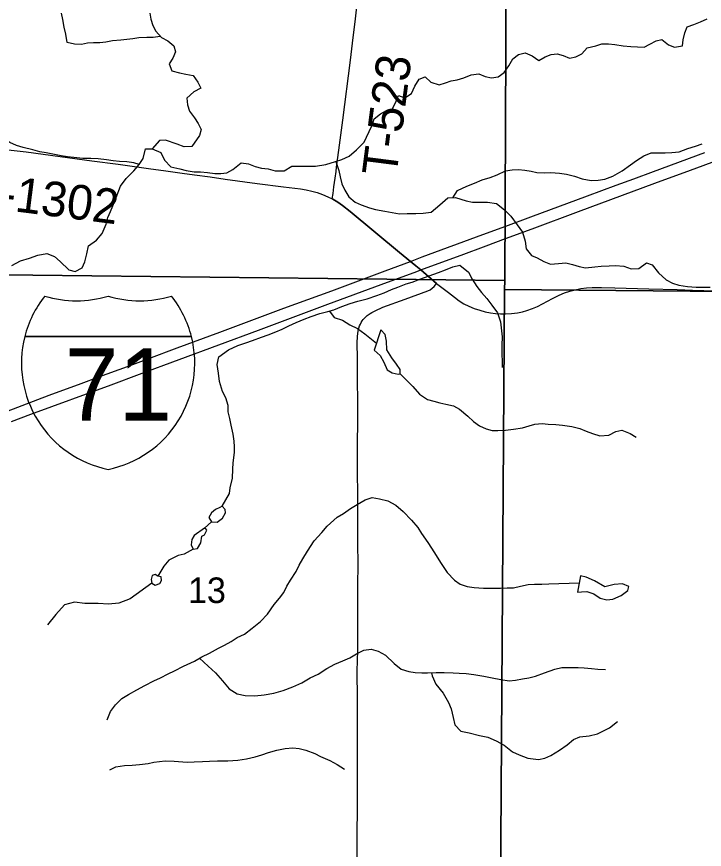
# Model space of a CAD drawing. Extents: x 0 to 34, y 0 to 22.
# Drawn here: x 10.791 to 11.919, y 10.337 to 11.702 of the extents above; entities that cross this region are included whole.
import ezdxf

# ---------------------------------------------------------------- set-up
doc = ezdxf.new("R2010")
doc.units = 0
for name, color, linetype in [('GM_X_County_Road', 7, 'Continuous'), ('GM_X_County_Road_Text', 7, 'Continuous'), ('GM_X_Interstate_Route', 7, 'Continuous'), ('GM_X_Interstate_Shield', 7, 'Continuous'), ('GM_X_Minor_Lake', 7, 'Continuous'), ('GM_X_Minor_River', 7, 'Continuous'), ('GM_X_Section', 7, 'Continuous'), ('GM_X_Section_Text', 7, 'Continuous'), ('GM_X_Township_Road', 7, 'Continuous'), ('GM_X_Township_Road_Text', 7, 'Continuous')]:
    doc.layers.add(name, color=color, linetype=linetype)

msp = doc.modelspace()

# ---------------------------------------------------------------- linework, layer by layer
at = {"layer": 'GM_X_County_Road'}
for points in [[(10.6295, 11.5003), (10.634, 11.4999), (10.6679, 11.4958), (10.7358, 11.4882), (10.782, 11.4831), (10.8067, 11.4801), (10.8621, 11.4725), (10.9144, 11.4654), (10.9576, 11.4597), (11.0073, 11.453), (11.0357, 11.449), (11.0621, 11.4454), (11.0825, 11.4426), (11.1082, 11.4391), (11.133, 11.4354), (11.1854, 11.4283), (11.2285, 11.4229), (11.2563, 11.4194), (11.2655, 11.4179), (11.2747, 11.4158), (11.2837, 11.4133), (11.2925, 11.4102), (11.3012, 11.4065), (11.3083, 11.403)], [(11.3083, 11.403), (11.3096, 11.4024), (11.3177, 11.3976), (11.3254, 11.3923), (11.3376, 11.3826), (11.4189, 11.3152), (11.4365, 11.3005), (11.4452, 11.2933), (11.4534, 11.2865), (11.4796, 11.2646)], [(11.4796, 11.2646), (11.4988, 11.2494), (11.5086, 11.2417), (11.5163, 11.2362), (11.5242, 11.2313), (11.5326, 11.227), (11.5412, 11.2234), (11.5502, 11.2204), (11.5593, 11.2181), (11.5678, 11.2163), (11.5762, 11.2152), (11.5841, 11.2147), (11.5924, 11.2145)], [(11.5924, 11.2145), (11.6025, 11.2152), (11.6119, 11.2165), (11.6203, 11.218), (11.6273, 11.2199), (11.6365, 11.2232), (11.6448, 11.2269), (11.6532, 11.2309), (11.6696, 11.2398), (11.6807, 11.2453), (11.6892, 11.2488), (11.698, 11.2518), (11.7069, 11.2542), (11.716, 11.256), (11.7252, 11.2571), (11.7345, 11.2576), (11.7499, 11.2577), (11.7716, 11.2571), (11.8275, 11.2555), (11.8741, 11.2543), (11.8989, 11.2535), (11.9362, 11.2521)]]:
    msp.add_lwpolyline(points, dxfattribs=at)
at = {"layer": 'GM_X_Interstate_Route'}
for points in [[(10.7745, 11.0548), (10.8442, 11.0812), (10.8967, 11.1005), (10.9258, 11.1112), (10.9725, 11.1284), (11.0074, 11.1415), (11.054, 11.159), (11.124, 11.1846), (11.1764, 11.2043), (11.2288, 11.2238), (11.3076, 11.2525), (11.395, 11.285), (11.4365, 11.3005), (11.4561, 11.3078), (11.5552, 11.3445), (11.5928, 11.3584), (11.6338, 11.3736), (11.7271, 11.408), (11.7737, 11.4253), (11.8029, 11.4361), (11.8349, 11.448), (11.9194, 11.4792)], [(10.7824, 11.038), (10.8144, 11.0501), (10.9457, 11.0984), (10.9922, 11.1158), (11.1876, 11.188), (11.24, 11.2073), (11.3011, 11.2303), (11.3886, 11.2625), (11.4469, 11.284), (11.4534, 11.2865), (11.476, 11.2949), (11.5198, 11.311), (11.5606, 11.326), (11.5927, 11.3379), (11.6363, 11.3541), (11.7121, 11.3823), (11.8374, 11.4286), (11.8957, 11.4501), (11.9773, 11.4804)]]:
    msp.add_lwpolyline(points, dxfattribs=at)
at = {"layer": 'GM_X_Interstate_Shield'}
for p, q in [((10.8043, 11.1773), (11.0775, 11.1773)), ((11.0775, 11.1773), (10.8043, 11.1773)), ((11.0775, 11.1773), (10.8043, 11.1773))]:
    msp.add_line(p, q, dxfattribs=at)
for centre, start, end in [((10.9764, 11.1337), 141.669, 165.8066), ((10.889, 11.4137), 253.0091, 286.9909), ((10.9928, 11.4137), 253.0091, 286.9909), ((10.9054, 11.1337), 14.1934, 38.331), ((10.9764, 11.1337), 165.8066, 258.463), ((10.9054, 11.1337), 281.537, 14.1934)]:
    msp.add_arc(centre, 0.1776, start, end, dxfattribs=at)
at = {"layer": 'GM_X_Minor_Lake'}
for points in [[(11.3771, 11.1552), (11.387, 11.1465), (11.3931, 11.1355), (11.3984, 11.1226), (11.4068, 11.1181), (11.4166, 11.1159), (11.42, 11.1162), (11.4196, 11.1234), (11.4139, 11.1322), (11.4059, 11.1424), (11.3979, 11.1556), (11.3971, 11.1697), (11.3952, 11.1807), (11.3883, 11.1882)], [(11.3883, 11.1882), (11.3771, 11.1552)], [(11.124, 10.8975), (11.1172, 10.8941), (11.1104, 10.8884), (11.1059, 10.8808), (11.1105, 10.8736), (11.1199, 10.8732), (11.1287, 10.8797), (11.1336, 10.8885), (11.1328, 10.8941), (11.128, 10.8996)], [(11.128, 10.8996), (11.124, 10.8975)], [(11.1029, 10.8603), (11.1013, 10.8625), (11.0992, 10.8632), (11.0821, 10.8511)], [(11.0821, 10.8511), (11.0783, 10.8447), (11.0772, 10.8359), (11.0802, 10.8291), (11.0875, 10.8299), (11.0927, 10.8394), (11.0946, 10.85), (11.0991, 10.8527), (11.1029, 10.8603)], [(11.0227, 10.7845), (11.0182, 10.7876), (11.0129, 10.786), (11.0117, 10.7792), (11.0125, 10.7731), (11.0182, 10.7701), (11.0258, 10.7728), (11.0284, 10.7777), (11.0277, 10.7834)], [(11.0277, 10.7834), (11.0227, 10.7845)], [(11.7105, 10.7586), (11.7173, 10.7593), (11.7261, 10.7594), (11.7371, 10.756), (11.7477, 10.7484), (11.7587, 10.7458), (11.7686, 10.747), (11.7819, 10.7531), (11.7932, 10.7611), (11.7947, 10.7679), (11.7845, 10.7721), (11.7704, 10.7709), (11.7553, 10.7671), (11.7385, 10.7769), (11.7245, 10.7833), (11.7154, 10.7855)], [(11.7154, 10.7855), (11.7105, 10.7586)]]:
    msp.add_lwpolyline(points, dxfattribs=at)
at = {"layer": 'GM_X_Minor_River'}
for points in [[(11.0265, 11.6694), (11.0146, 11.6673), (11.0044, 11.6677), (10.9911, 11.6671), (10.9813, 11.6653), (10.9616, 11.6632), (10.9483, 11.6618), (10.9373, 11.66), (10.9275, 11.6586), (10.9172, 11.6587), (10.907, 11.6581), (10.8975, 11.6563), (10.8858, 11.6568), (10.8737, 11.6591), (10.8715, 11.6728), (10.8686, 11.6842), (10.8668, 11.6972), (10.8643, 11.7074)], [(11.0093, 11.7075), (11.0111, 11.6973), (11.0144, 11.6874), (11.0189, 11.6778), (11.0283, 11.6675), (11.0388, 11.6621), (11.0486, 11.6537), (11.0515, 11.6438), (11.0469, 11.6339), (11.0411, 11.6241), (11.0456, 11.6131), (11.0577, 11.6095), (11.0686, 11.6075), (11.0804, 11.6052), (11.0882, 11.5945), (11.0931, 11.5845), (11.0813, 11.5782), (11.0702, 11.5681), (11.0712, 11.5574), (11.0742, 11.5468), (11.0828, 11.5361), (11.0888, 11.5265), (11.0936, 11.517), (11.0909, 11.5068)], [(11.3605, 11.4959), (11.3727, 11.5219), (11.377, 11.534), (11.3873, 11.5426), (11.3972, 11.5478), (11.4067, 11.55), (11.4121, 11.5602), (11.4171, 11.5723), (11.4277, 11.5688), (11.4383, 11.5759), (11.4441, 11.588), (11.451, 11.5993), (11.4605, 11.603), (11.4703, 11.5945), (11.4839, 11.5898), (11.4941, 11.5932), (11.5036, 11.5965), (11.5135, 11.5983), (11.5241, 11.6012), (11.5363, 11.6064), (11.5488, 11.6082), (11.5593, 11.6035), (11.5695, 11.6012), (11.5802, 11.6033), (11.5901, 11.6104), (11.5977, 11.621), (11.6043, 11.6323), (11.6138, 11.6394), (11.6248, 11.6424), (11.6361, 11.6377), (11.647, 11.6296), (11.6573, 11.6356), (11.6672, 11.6397), (11.677, 11.6407), (11.6869, 11.638), (11.6974, 11.6337), (11.708, 11.6359), (11.7179, 11.6407), (11.7263, 11.6505), (11.7408, 11.6541), (11.7503, 11.6571), (11.7612, 11.6573), (11.7718, 11.6561), (11.7854, 11.6541), (11.7979, 11.6528), (11.8089, 11.6523), (11.8199, 11.6515), (11.8294, 11.6567), (11.8393, 11.6623), (11.8491, 11.6641), (11.8597, 11.6553), (11.8695, 11.6517), (11.8828, 11.6539), (11.8836, 11.6637), (11.8867, 11.6751), (11.8906, 11.6849), (11.9012, 11.689), (11.9122, 11.6931), (11.9233, 11.6983)], [(10.9919, 11.4595), (10.9832, 11.4621), (10.9718, 11.4639), (10.9593, 11.4643), (10.9494, 11.4654), (10.938, 11.4669), (10.9244, 11.4687), (10.9126, 11.4691), (10.8997, 11.4694), (10.8849, 11.4709), (10.8743, 11.472), (10.864, 11.4735), (10.8504, 11.4765), (10.8394, 11.4787), (10.8291, 11.4802), (10.8173, 11.4832), (10.8018, 11.4873), (10.7908, 11.4907), (10.7797, 11.4952), (10.7652, 11.5046)], [(11.0909, 11.5068), (11.0783, 11.4887), (11.0658, 11.4881), (11.054, 11.4927), (11.035, 11.4994), (11.0252, 11.4987), (11.0131, 11.4853)], [(10.783, 11.2938), (10.7974, 11.3014), (10.8118, 11.306), (10.8258, 11.311), (10.8406, 11.3137), (10.8528, 11.3088), (10.8623, 11.3004), (10.8763, 11.2865), (10.887, 11.2838), (10.8983, 11.2899), (10.9028, 11.2998), (10.9058, 11.3131), (10.9085, 11.326), (10.9217, 11.3355), (10.9312, 11.3462), (10.9379, 11.3614), (10.9402, 11.3724), (10.9447, 11.3823), (10.9489, 11.3918), (10.9541, 11.4051), (10.9613, 11.4237), (10.9707, 11.4366), (10.9832, 11.4492), (10.9919, 11.4595), (10.9983, 11.4693), (11.0024, 11.4849), (11.0131, 11.4853), (11.0275, 11.4789), (11.0332, 11.4664), (11.0439, 11.4558), (11.0587, 11.4525), (11.0689, 11.4494), (11.0822, 11.4476), (11.0925, 11.4472), (11.1038, 11.4465), (11.116, 11.4447), (11.1258, 11.4447), (11.1353, 11.4459), (11.1452, 11.4512), (11.1592, 11.4622), (11.1709, 11.4604), (11.182, 11.4559), (11.1926, 11.4532), (11.2032, 11.4521), (11.2146, 11.4491), (11.2294, 11.4492), (11.2423, 11.4568), (11.2563, 11.4565), (11.281, 11.4565), (11.298, 11.4596), (11.3139, 11.4642), (11.3242, 11.4677), (11.3363, 11.473), (11.348, 11.4833), (11.3605, 11.4959)], [(11.5064, 11.405), (11.514, 11.417), (11.5291, 11.4239), (11.5416, 11.4289), (11.5545, 11.4342), (11.5674, 11.4381), (11.5788, 11.4427), (11.5924, 11.4488), (11.6034, 11.4507), (11.614, 11.4511), (11.6243, 11.45), (11.6345, 11.4485), (11.644, 11.4463), (11.6558, 11.4459), (11.6668, 11.446), (11.6812, 11.4453), (11.6926, 11.4438), (11.7055, 11.44), (11.718, 11.4359), (11.7328, 11.4333), (11.7442, 11.4337), (11.7552, 11.4352), (11.7685, 11.4402), (11.7836, 11.449), (11.7972, 11.4589), (11.8075, 11.4661), (11.8192, 11.4738), (11.8313, 11.4784), (11.8541, 11.4784), (11.8651, 11.4792), (11.8772, 11.4804), (11.8916, 11.4854), (11.9041, 11.4896), (11.9147, 11.4934)], [(11.3143, 11.4644), (11.3193, 11.4495), (11.3212, 11.4392), (11.3243, 11.4278), (11.3289, 11.4172), (11.3357, 11.4066), (11.346, 11.3976), (11.3559, 11.3934), (11.3695, 11.3885), (11.3794, 11.3859), (11.3946, 11.3829), (11.4067, 11.3807), (11.4189, 11.3788), (11.4314, 11.3792), (11.4454, 11.3793), (11.4576, 11.3797), (11.4708, 11.3812), (11.4848, 11.3934), (11.4977, 11.4045), (11.5106, 11.4053), (11.5281, 11.4), (11.5383, 11.3978), (11.5516, 11.3974), (11.563, 11.3975), (11.5778, 11.3952), (11.5911, 11.385), (11.601, 11.3748), (11.6116, 11.3604), (11.6204, 11.3483), (11.6246, 11.3335), (11.6266, 11.3214), (11.6349, 11.31), (11.6444, 11.3066), (11.6554, 11.3006), (11.6661, 11.2961), (11.6794, 11.2973), (11.6915, 11.2981), (11.7021, 11.2954), (11.7131, 11.2921), (11.7238, 11.2902), (11.7389, 11.2918), (11.7492, 11.2926), (11.7624, 11.2934), (11.7731, 11.2938), (11.7867, 11.2927), (11.7985, 11.2885), (11.811, 11.2889), (11.8235, 11.2981), (11.833, 11.2947), (11.8436, 11.2818), (11.8562, 11.2701), (11.8661, 11.2648), (11.8767, 11.2618), (11.8908, 11.2596), (11.9052, 11.2585), (11.9173, 11.2582), (11.9283, 11.2586)], [(11.128, 10.8996), (11.1399, 10.92), (11.141, 10.9295), (11.1448, 10.9454), (11.1455, 10.9602), (11.1462, 10.9705), (11.1484, 10.9872), (11.1484, 10.9966), (11.1476, 11.0061), (11.1457, 11.0175), (11.1426, 11.0323), (11.1403, 11.0429), (11.138, 11.0543), (11.1376, 11.0645), (11.1338, 11.077), (11.1284, 11.0873), (11.1238, 11.1036), (11.1219, 11.1172), (11.1199, 11.1316), (11.1222, 11.1442), (11.1385, 11.1556), (11.1536, 11.1629), (11.1669, 11.1671), (11.1779, 11.1709), (11.1926, 11.1766), (11.2033, 11.1801), (11.2158, 11.185), (11.2264, 11.1893), (11.2373, 11.195), (11.2491, 11.2007), (11.2624, 11.2061), (11.2741, 11.2103), (11.2881, 11.2152), (11.301, 11.2183), (11.3112, 11.2214), (11.3241, 11.2264), (11.3378, 11.2317), (11.3503, 11.2355), (11.3658, 11.2394), (11.3817, 11.2448), (11.3935, 11.2493), (11.4056, 11.2547), (11.4162, 11.2585), (11.4298, 11.2639), (11.4393, 11.2666), (11.4522, 11.2715), (11.4674, 11.2769), (11.4829, 11.2823), (11.4943, 11.2868), (11.5064, 11.2914), (11.5174, 11.2945), (11.5318, 11.2832), (11.5379, 11.2714), (11.5456, 11.2597), (11.5532, 11.2495), (11.5619, 11.2396), (11.5699, 11.2286), (11.5794, 11.2165), (11.5844, 11.2017), (11.586, 11.1866), (11.5868, 11.1767), (11.5864, 11.1634), (11.5865, 11.149), (11.5869, 11.1361), (11.5873, 11.1266)], [(11.3038, 11.2191), (11.3117, 11.2085), (11.325, 11.204), (11.3371, 11.1968), (11.35, 11.1904), (11.3618, 11.1817), (11.3809, 11.1664)], [(11.42, 11.1164), (11.4406, 11.0954), (11.4516, 11.0829), (11.4645, 11.0743), (11.4748, 11.0716), (11.4847, 11.069), (11.4949, 11.0664), (11.5074, 11.0638), (11.5173, 11.0585), (11.5306, 11.0471), (11.5401, 11.0384), (11.5496, 11.0313), (11.561, 11.026), (11.5705, 11.0237), (11.58, 11.0234), (11.5925, 11.0242), (11.6054, 11.0254), (11.6202, 11.0277), (11.6312, 11.0311), (11.6407, 11.0338), (11.6524, 11.035), (11.6623, 11.0339), (11.6748, 11.0335), (11.6858, 11.0324), (11.7014, 11.0298), (11.7143, 11.0268), (11.7245, 11.0223), (11.7352, 11.0186), (11.7469, 11.0148), (11.7617, 11.016), (11.7735, 11.0217), (11.7833, 11.024), (11.797, 11.0184), (11.8065, 11.0123)], [(10.9392, 10.549), (10.9449, 10.5627), (10.9532, 10.5737), (10.9634, 10.584), (10.9744, 10.5909), (10.988, 10.5985), (11.0012, 10.6057), (11.016, 10.613), (11.027, 10.618), (11.0391, 10.6248), (11.0497, 10.6298), (11.0645, 10.6371), (11.0823, 10.6455), (11.0944, 10.6523), (11.1069, 10.6584), (11.1217, 10.6665), (11.1315, 10.6714), (11.1429, 10.6775), (11.1527, 10.684), (11.1645, 10.6897), (11.177, 10.6993), (11.1906, 10.7103), (11.2023, 10.7225), (11.2133, 10.7381), (11.222, 10.7487), (11.2288, 10.7582), (11.2341, 10.7681), (11.2397, 10.778), (11.2492, 10.7924), (11.2541, 10.8027), (11.2601, 10.8133), (11.268, 10.8255), (11.279, 10.8426), (11.2915, 10.8563), (11.3001, 10.8666), (11.3164, 10.8814), (11.327, 10.8875), (11.3384, 10.8955), (11.3494, 10.9024), (11.3626, 10.91), (11.3736, 10.9135), (11.3857, 10.9116), (11.3998, 10.9082), (11.4127, 10.9011), (11.4249, 10.8909), (11.4382, 10.8765), (11.4489, 10.8644), (11.455, 10.8545), (11.4652, 10.8398), (11.4763, 10.8231), (11.4858, 10.8072), (11.4969, 10.7909), (11.5087, 10.7781), (11.5182, 10.7716), (11.5299, 10.7679), (11.5413, 10.7664), (11.5565, 10.7653), (11.5705, 10.7653), (11.5842, 10.765), (11.5952, 10.7654), (11.6054, 10.7658), (11.6172, 10.7681), (11.6297, 10.7712), (11.6399, 10.7716), (11.6521, 10.7717), (11.6638, 10.7721), (11.7132, 10.7737)], [(11.1105, 10.8736), (11.0992, 10.8632)], [(11.0802, 10.8291), (11.0655, 10.8207), (11.056, 10.8184), (11.0405, 10.8108), (11.0325, 10.8013), (11.0227, 10.7845)], [(11.0125, 10.7731), (10.9769, 10.7476), (10.9584, 10.7407), (10.9413, 10.7391), (10.9246, 10.7398), (10.903, 10.7398), (10.8859, 10.742), (10.8692, 10.7378), (10.8552, 10.7218), (10.8416, 10.7047)], [(11.091, 10.6504), (11.1051, 10.6372), (11.1169, 10.6262), (11.1287, 10.613), (11.1393, 10.6001), (11.1526, 10.5918), (11.1659, 10.5892), (11.1815, 10.5888), (11.1966, 10.5904), (11.2126, 10.5931), (11.2281, 10.5973), (11.244, 10.6031), (11.2584, 10.61), (11.2724, 10.618), (11.2853, 10.6241), (11.2993, 10.6332), (11.3126, 10.6405), (11.3255, 10.6458), (11.3372, 10.6508), (11.3482, 10.6573), (11.3603, 10.6634), (11.3724, 10.6653), (11.3838, 10.6616), (11.396, 10.6551), (11.4101, 10.6415), (11.4215, 10.6321), (11.434, 10.6283), (11.4442, 10.6268), (11.4552, 10.6261), (11.4647, 10.6265), (11.4788, 10.6266), (11.4917, 10.6266), (11.5068, 10.6263), (11.5163, 10.6255), (11.5281, 10.6252), (11.5406, 10.6237), (11.5569, 10.6207), (11.5706, 10.6181), (11.5846, 10.6151), (11.5983, 10.6133), (11.6089, 10.6141), (11.6203, 10.6164), (11.6309, 10.6183), (11.6419, 10.621), (11.6567, 10.6264), (11.6733, 10.6321), (11.6851, 10.6348), (11.6984, 10.6352), (11.7116, 10.6349), (11.7215, 10.6345), (11.7337, 10.6334), (11.7439, 10.6323), (11.7564, 10.6316)], [(11.4712, 10.6265), (11.472, 10.6216), (11.4781, 10.6076), (11.4902, 10.5928), (11.499, 10.5777), (11.5036, 10.5671), (11.5067, 10.553), (11.5094, 10.5409), (11.5193, 10.5307), (11.5329, 10.5277), (11.55, 10.5236), (11.5637, 10.5206), (11.577, 10.5149), (11.5903, 10.5078), (11.6039, 10.4968), (11.615, 10.4919), (11.629, 10.4866), (11.6465, 10.4844), (11.6571, 10.4867), (11.6669, 10.4909), (11.6813, 10.4993), (11.6938, 10.5085), (11.704, 10.5168), (11.7146, 10.5214), (11.7298, 10.523), (11.7431, 10.5261), (11.7533, 10.531), (11.7631, 10.5364), (11.776, 10.5463)], [(10.9436, 10.4671), (10.9538, 10.472), (10.9675, 10.4744), (10.9804, 10.4748), (10.9921, 10.476), (11.0066, 10.4779), (11.016, 10.4798), (11.0342, 10.4822), (11.049, 10.4814), (11.0707, 10.48), (11.082, 10.4804), (11.0957, 10.4812), (11.1074, 10.4816), (11.1203, 10.482), (11.137, 10.4821), (11.1537, 10.4829), (11.1677, 10.4852), (11.1818, 10.4887), (11.1928, 10.4921), (11.2038, 10.496), (11.2174, 10.4998), (11.231, 10.5021), (11.2436, 10.5033), (11.2542, 10.5022), (11.2652, 10.4996), (11.2796, 10.4939), (11.2891, 10.4894), (11.3043, 10.4826), (11.3165, 10.4758), (11.3286, 10.4683)]]:
    msp.add_lwpolyline(points, dxfattribs=at)
at = {"layer": 'GM_X_Section'}
for points in [[(11.5966, 12.2962), (12.6535, 12.2476), (12.6265, 11.2451), (11.591, 11.2544), (11.5914, 11.2691), (11.5959, 12.2894)], [(11.5959, 12.2894), (11.5914, 11.2691), (10.6237, 11.2801), (10.6374, 12.2875)], [(10.6237, 11.2801), (11.5914, 11.2691), (11.591, 11.2544), (11.5843, 10.269), (10.6178, 10.275)], [(11.591, 11.2544), (12.6265, 11.2451), (12.599, 10.2335), (11.5847, 10.2523), (11.5843, 10.269)]]:
    msp.add_lwpolyline(points, close=True, dxfattribs=at)
at = {"layer": 'GM_X_Township_Road'}
for points in [[(11.3146, 11.448), (11.3156, 11.4548), (11.3191, 11.4826), (11.3256, 11.5318), (11.3381, 11.6304), (11.3414, 11.6581), (11.3463, 11.6982), (11.3509, 11.7382)], [(11.3083, 11.403), (11.3097, 11.4119), (11.3111, 11.4229), (11.313, 11.4372), (11.3146, 11.448)], [(11.4796, 11.2646), (11.4534, 11.2865), (11.4452, 11.2933), (11.4365, 11.3005), (11.4189, 11.3152), (11.3376, 11.3826), (11.3254, 11.3923), (11.3177, 11.3976), (11.3096, 11.4024), (11.3083, 11.403)], [(11.3495, 11.1596), (11.3494, 11.1679), (11.3496, 11.1771), (11.3502, 11.1832), (11.3514, 11.1892), (11.3533, 11.195), (11.3545, 11.1978), (11.3559, 11.2005), (11.3575, 11.203), (11.3593, 11.2055), (11.3613, 11.2078), (11.3635, 11.2099), (11.3657, 11.2119), (11.3707, 11.2154), (11.3734, 11.217), (11.3789, 11.2197), (11.3912, 11.2253), (11.4281, 11.2389), (11.4652, 11.2525), (11.4691, 11.2541), (11.4724, 11.2565), (11.4756, 11.2595), (11.4796, 11.2646)], [(11.3493, 10.3185), (11.3494, 10.3455), (11.3494, 10.3642), (11.3497, 10.4015), (11.35, 10.4388), (11.3499, 10.4606), (11.3497, 10.4823), (11.3497, 10.4947), (11.3499, 10.5225), (11.3496, 10.5443), (11.3498, 10.5813), (11.3496, 10.5976), (11.3493, 10.6152), (11.3492, 10.63), (11.3498, 10.6456), (11.3502, 10.6642), (11.3502, 10.6782), (11.3504, 10.6953), (11.3505, 10.7109), (11.3504, 10.714), (11.3504, 10.7171), (11.3502, 10.7357), (11.3501, 10.7481), (11.3502, 10.7605), (11.3505, 10.776), (11.3509, 10.7978), (11.3507, 10.8134), (11.3505, 10.8289), (11.3506, 10.8445), (11.3504, 10.8631), (11.3503, 10.8755), (11.3504, 10.8911), (11.3503, 10.9128), (11.3502, 10.9253), (11.3497, 10.9494), (11.3496, 10.9676), (11.35, 10.9936), (11.3502, 11.0465), (11.3502, 11.0714), (11.3499, 11.1056), (11.3498, 11.1274), (11.3496, 11.1492), (11.3495, 11.1596)]]:
    msp.add_lwpolyline(points, dxfattribs=at)

# ---------------------------------------------------------------- texts
at = {"layer": 'GM_X_County_Road_Text'}
msp.add_text('C-1302', height=0.05682, rotation=352.7357, dxfattribs=at).set_placement((10.7071, 11.3928))
at = {"layer": 'GM_X_Interstate_Shield'}
msp.add_text('71', height=0.11837, dxfattribs=at).set_placement((10.8697, 11.0397))
at = {"layer": 'GM_X_Section_Text'}
msp.add_text('13', height=0.04186, rotation=0, dxfattribs=at).set_placement((11.0718, 10.7407))
at = {"layer": 'GM_X_Township_Road_Text'}
msp.add_text('T-523', height=0.05682, rotation=82.7008, dxfattribs=at).set_placement((11.4134, 11.4385))

doc.saveas('drawing.dxf')
